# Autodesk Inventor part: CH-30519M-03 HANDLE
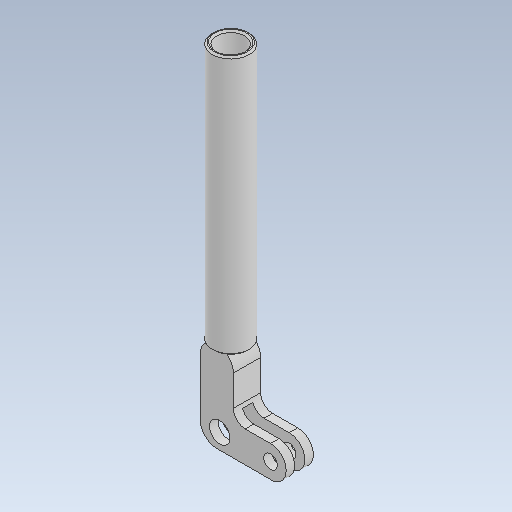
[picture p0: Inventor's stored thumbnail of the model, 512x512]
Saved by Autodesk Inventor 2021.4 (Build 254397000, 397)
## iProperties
Created: 2017-11
Part Number: CH-30519M-03 HANDLE
Material: Ogólny
Document SubType Name: Modeling
Designer: user
Density: 1 g/cm^3
Appearance: Domyślna
Author: user
Revision Number: ÈÎºÎ
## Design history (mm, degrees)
feature "À­Éì2"
feature "µ¹½Ç1"
node "Bryła1"
node "Bryła2"
